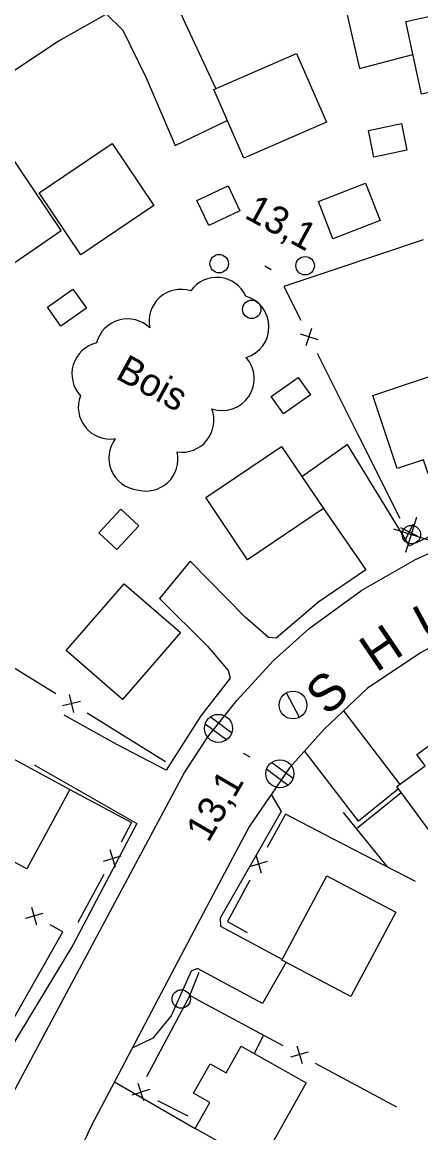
# Model space of a CAD drawing. Extents: x 219136 to 222520, y 5421589 to 5424530.
# Drawn here: x 220625.8 to 220669, y 5423672.5 to 5423792.9 of the extents above; entities that cross this region are included whole.
import ezdxf

# ---------------------------------------------------------------- set-up
doc = ezdxf.new("R2010")
doc.units = 0
for name, color, linetype in [('Level 19', 7, 'Continuous'), ('Level 21', 7, 'Continuous'), ('Level 3', 7, 'Continuous'), ('Level 31', 7, 'Continuous'), ('Level 36', 7, 'Continuous'), ('Level 37', 7, 'Continuous'), ('Level 44', 7, 'Continuous')]:
    doc.layers.add(name, color=color, linetype=linetype)

msp = doc.modelspace()

# ---------------------------------------------------------------- linework, layer by layer
at = {"layer": 'Level 19'}
for points in [[(220658.59, 5423804.12), (220662.31, 5423787.92), (220668.11, 5423789.43)], [(220646.76, 5423785.73), (220642.46, 5423794.96), (220642.32, 5423797.52)], [(220634.91, 5423793.81), (220636.68, 5423792.05), (220639.18, 5423786.88), (220642.34, 5423779.56), (220647.99, 5423782.28)], [(220615.69, 5423781.1), (220624.85, 5423766.81), (220629.97, 5423770.35), (220623.99, 5423779.28), (220620.8, 5423784.94)], [(220667.75, 5423736.15), (220661.02, 5423747.14), (220656.08, 5423743.64)], [(220658.42, 5423740.18), (220663, 5423733.52)], [(220653.29, 5423726.14), (220652.44, 5423726.19), (220649.91, 5423728.39), (220643.98, 5423734.49), (220640.63, 5423730.44), (220645.86, 5423725.27), (220648.09, 5423722.63), (220648.32, 5423721.77)], [(220641.36, 5423711.8), (220636.01, 5423714.61), (220630.29, 5423717.79)], [(220660.58, 5423718.23), (220666.7, 5423710.27)], [(220666.56, 5423709.78), (220662.23, 5423706.26), (220656.37, 5423713.9)], [(220627.07, 5423712.37), (220638.17, 5423706.04)], [(220647.22, 5423695.77), (220647.25, 5423694.88), (220653.96, 5423691.29)], [(220654.38, 5423690.97), (220651.79, 5423686.5), (220644.77, 5423690.31), (220644.09, 5423690)], [(220635.76, 5423677.99), (220644.5, 5423672.96)]]:
    msp.add_lwpolyline(points, dxfattribs=at)
at = {"layer": 'Level 21'}
for points in [[(220669.68, 5423806.84), (220660.39, 5423804.75), (220652.23, 5423801.9), (220645.45, 5423799.02), (220636.74, 5423794.84), (220629.7, 5423790.89), (220619.55, 5423784.1), (220612.35, 5423778.5), (220603.84, 5423770.57), (220598.87, 5423764.98), (220591.71, 5423755.97), (220585.72, 5423746.99), (220580.84, 5423738.67), (220574.26, 5423725.79), (220564.52, 5423707.81), (220564.43, 5423705.76), (220564.95, 5423703.39), (220566.15, 5423701.13), (220567.68, 5423699), (220569.93, 5423697.64), (220593.02, 5423685.57)], [(220678.04, 5423740.33), (220672.38, 5423738.26), (220667.75, 5423736.15)], [(220593.02, 5423685.57), (220616.56, 5423672.83), (220619.48, 5423672.53), (220621.29, 5423673.14), (220622.82, 5423674.1), (220624, 5423675.51), (220625.02, 5423677.3), (220643.31, 5423711.47), (220645.87, 5423715.41), (220649.04, 5423719.35), (220652.97, 5423723.67), (220656.88, 5423727.19), (220662.59, 5423731.34), (220668.41, 5423734.65), (220674.53, 5423737.49)], [(220663, 5423733.52), (220657.92, 5423730.06), (220653.29, 5423726.14)], [(220674.18, 5423727.36), (220668.93, 5423724.55), (220663.15, 5423720.65), (220658.49, 5423716.25), (220654.72, 5423712.07), (220650.41, 5423705.74), (220646.77, 5423698.94), (220642.67, 5423691.14), (220633.28, 5423673.26)], [(220648.32, 5423721.77), (220645.12, 5423717.69), (220641.36, 5423711.8)], [(220652.75, 5423709.17), (220653.82, 5423707.34), (220647.22, 5423695.77)], [(220638.17, 5423706.04), (220631.26, 5423692.82), (220621.5, 5423676.73), (220619.21, 5423675.39), (220616.88, 5423675.31), (220612.89, 5423676.92), (220608.39, 5423679.29)], [(220644.09, 5423690), (220641.9, 5423685.16), (220639.91, 5423682.76), (220637.69, 5423681.66)], [(220633.28, 5423673.26), (220631.81, 5423670.17), (220631.65, 5423667.65), (220632.53, 5423665.32), (220634.52, 5423663.18), (220640.34, 5423660.19), (220680.65, 5423639.06)]]:
    msp.add_lwpolyline(points, dxfattribs=at)
at = {"layer": 'Level 3'}
for p, q in [((220652.06, 5423766.49), (220652.75, 5423766.11)), ((220649.72, 5423713.64), (220650.42, 5423713.26))]:
    msp.add_line(p, q, dxfattribs=at)
at = {"layer": 'Level 31'}
for points in [[(220667.33, 5423793), (220676.87, 5423795.09), (220678.59, 5423787.22), (220669.05, 5423785.13)], [(220646.53, 5423785.63), (220655.5, 5423789.52), (220658.74, 5423782.08), (220649.77, 5423778.18)], [(220667.46, 5423779.04), (220663.87, 5423778.3), (220663.28, 5423781.19), (220666.87, 5423781.93)], [(220627.59, 5423774.42), (220635.5, 5423779.76), (220640.04, 5423773.04), (220632.13, 5423767.7)], [(220664.55, 5423771.42), (220659.43, 5423769.43), (220657.86, 5423773.48), (220662.98, 5423775.47)], [(220649.36, 5423772.47), (220645.98, 5423770.87), (220644.69, 5423773.59), (220648.07, 5423775.19)], [(220632.71, 5423761.92), (220629.94, 5423759.97), (220628.49, 5423762.03), (220631.26, 5423763.99)], [(220663.75, 5423752.44), (220673.57, 5423755.74), (220676.16, 5423748.04), (220672.77, 5423746.9), (220673.36, 5423745.15), (220669.77, 5423743.94), (220669.26, 5423745.46), (220666.42, 5423744.51)], [(220652.74, 5423752.33), (220655.67, 5423754.41), (220657.02, 5423752.51), (220654.09, 5423750.44)], [(220645.65, 5423741.37), (220653.87, 5423746.91), (220658.42, 5423740.18), (220650.19, 5423734.63)], [(220638.4, 5423738.3), (220636.01, 5423735.73), (220634.07, 5423737.54), (220636.46, 5423740.11)], [(220630.53, 5423724.79), (220636.81, 5423732.03), (220642.92, 5423726.74), (220636.64, 5423719.49)], [(220679.99, 5423709.95), (220671.16, 5423703.5), (220666.38, 5423710.03), (220669.43, 5423712.27), (220668.54, 5423713.49), (220671.56, 5423715.7), (220672.49, 5423714.43), (220675.24, 5423716.44)], [(220619.07, 5423705.02), (220623.74, 5423713.62), (220630.92, 5423709.72), (220626.25, 5423701.12)], [(220653.92, 5423691.22), (220658.77, 5423700.36), (220666.25, 5423696.39), (220661.4, 5423687.25)], [(220656.55, 5423677.89), (220651.54, 5423668.99), (220644.5, 5423672.96), (220646.08, 5423675.77), (220644.33, 5423676.76), (220646.14, 5423679.96), (220647.87, 5423678.99), (220649.49, 5423681.87)]]:
    msp.add_lwpolyline(points, close=True, dxfattribs=at)
at = {"layer": 'Level 36'}
for p, q in [((220667.36, 5423735.45), (220668.53, 5423739.26)), ((220669.85, 5423736.77), (220666.04, 5423737.94)), ((220655.82, 5423717.53), (220654.42, 5423720.19)), ((220648.46, 5423715.86), (220646.13, 5423717.59)), ((220645.6, 5423716.84), (220647.93, 5423715.11)), ((220655.12, 5423710.92), (220652.8, 5423712.65)), ((220652.26, 5423711.9), (220654.58, 5423710.17))]:
    msp.add_line(p, q, dxfattribs=at)
for centre, radius in [((220647.11, 5423766.74), 1), ((220656.43, 5423766.52), 1), ((220650.64, 5423761.79), 1), ((220667.95, 5423737.36), 1), ((220655.11, 5423718.87), 1.5), ((220647.03, 5423716.34), 1.52), ((220653.69, 5423711.42), 1.52), ((220643, 5423686.99), 1)]:
    msp.add_circle(centre, radius, dxfattribs=at)
at = {"layer": 'Level 37'}
for p, q in [((220656.53, 5423757.86), (220657.17, 5423759.76)), ((220655.9, 5423759.13), (220657.8, 5423758.5)), ((220668.6, 5423737.2), (220666.82, 5423738.1)), ((220667.26, 5423736.75), (220668.16, 5423738.54)), ((220630.86, 5423720.01), (220631.32, 5423718.06)), ((220632.07, 5423719.26), (220630.12, 5423718.8)), ((220635.24, 5423703.2), (220635.82, 5423701.29)), ((220634.57, 5423701.95), (220636.49, 5423702.53)), ((220650.42, 5423701.36), (220652.34, 5423701.93)), ((220651.09, 5423702.61), (220651.66, 5423700.69)), ((220626.76, 5423696.95), (220627.32, 5423695.03)), ((220628, 5423696.27), (220626.08, 5423695.71)), ((220655.52, 5423681.91), (220656.09, 5423679.99)), ((220656.76, 5423681.24), (220654.84, 5423680.67)), ((220638.95, 5423675.94), (220638.32, 5423677.84)), ((220637.69, 5423676.58), (220639.59, 5423677.21))]:
    msp.add_line(p, q, dxfattribs=at)
for points in [[(220669.22, 5423769.33), (220659.74, 5423766.14)], [(220659.74, 5423766.14), (220654.13, 5423764.25), (220655.95, 5423760.6)], [(220657.74, 5423757.02), (220662.22, 5423748.08)], [(220662.22, 5423748.08), (220666.69, 5423739.13)], [(220629.39, 5423720.08), (220620.89, 5423725.34)], [(220641.3, 5423712.72), (220632.79, 5423717.98)], [(220630.92, 5423709.72), (220637.61, 5423706.13), (220636.47, 5423704.01)], [(220661.99, 5423705.5), (220666.85, 5423709.38)], [(220659.5, 5423704.34), (220654.29, 5423707.04), (220652.33, 5423703.41)], [(220665.36, 5423701.31), (220660.6, 5423707.23)], [(220668.38, 5423699.75), (220659.5, 5423704.34)], [(220634.59, 5423700.48), (220631.8, 5423695.28)], [(220650.43, 5423699.89), (220648, 5423695.4), (220650.15, 5423694.22)], [(220626, 5423686.93), (220630.16, 5423694.28), (220628.79, 5423695.03)], [(220645.24, 5423686.66), (220643.92, 5423687.37), (220644.93, 5423689.89)], [(220643.93, 5423687.36), (220639.22, 5423678.54)], [(220621.07, 5423678.23), (220626, 5423686.93)], [(220654.04, 5423681.9), (220645.24, 5423686.66)], [(220651.92, 5423683.05), (220650.89, 5423681.08)], [(220666.36, 5423675.25), (220657.56, 5423680)], [(220640.42, 5423675.99), (220643.73, 5423674.33)]]:
    msp.add_lwpolyline(points, dxfattribs=at)
at = {"layer": 'Level 44'}
for centre, start, end in [((220646.85, 5423761.79), 24.4159, 144.4159), ((220642.97, 5423760.5), 72.2469, 192.2469), ((220649.05, 5423759.89), 286.7696, 74.034), ((220637.17, 5423757.29), 45.6713, 165.6713), ((220634.6, 5423754.77), 103.0606, 223.0606), ((220647.46, 5423754.28), 250.7171, 41.535), ((220635.3, 5423751.18), 159.1358, 279.1358), ((220643.08, 5423749.75), 261.2674, 21.2674), ((220638.61, 5423745.66), 142.8152, 262.8152), ((220639.18, 5423745.54), 253.1119, 13.1119)]:
    msp.add_arc(centre, 3.46, start, end, dxfattribs=at)

# ---------------------------------------------------------------- texts
at = {"layer": 'Level 21'}
for s, rotation, p in [('U', 28.1574, (220669.63, 5423725.68)), ('H', 34.0091, (220664.15, 5423722.35)), ('S', 43.3562, (220658.86, 5423717.58))]:
    msp.add_text(s, height=4, rotation=rotation, dxfattribs=at).set_placement(p)
at = {"layer": 'Level 3'}
for rotation, p in [(331.383, (220649.73, 5423771.77)), (59.72, (220645.94, 5423703.86))]:
    msp.add_text('13,1', height=3, rotation=rotation, dxfattribs=at).set_placement(p)
at = {"layer": 'Level 44'}
msp.add_text('Bois', height=3, rotation=331.3547, dxfattribs=at).set_placement((220635.75, 5423754.36))

doc.saveas('drawing.dxf')
